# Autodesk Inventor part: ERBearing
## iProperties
Author: Administrator
Shininess: 60.0
PropertySet Name: _Private Model Information
Created: 2001-01
Part Number: ERBearing
Document SubType Name: Modeling
Designer: Administrator
Material: Steel, High Strength Low Alloy
Control State: 0
Master: False
Checked Out: False
PropertySet Name: Design Tracking Control
Density: 7.84
Volumn: 37.54205912555258
Area: 119.17640985544239
PropertySet Name: Model Information
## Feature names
1. Revolution1
2. Hole1
3. Snap Ring [Revolution]
4. Hole Pattern [Circular Pattern]
5. Shield1 [Extrusion]
6. Shield2 [Extrusion]
